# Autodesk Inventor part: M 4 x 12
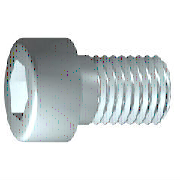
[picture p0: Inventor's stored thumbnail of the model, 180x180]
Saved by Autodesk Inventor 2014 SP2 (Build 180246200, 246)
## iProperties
IsCustomPart: 0
Created: 2009-02
Part Number: M 4 x 12
Material: 강, 연강
Description: 6각머리 태핑 나사
Document SubType Name: Modeling
Standard: KS B 1003
Designer: KYOUNG IL JANG
Standards Organization: KS
Language: ko-KR
Size Designation: M 4 x 12
Categories: <MemberInstance><Categories><Category DisplayName="조임쇠" InternalName="e4da775c-781d-43d5-af7c-5136215cf5a6" Mnemonic="FSTN"><Category DisplayName="볼트" InternalN
Density: 7.86 g/cm^3
Mass: 2.23465 g
Surface Area: 3.30853 cm^2
Volume: 0.284306 cm^3
Appearance: 강철
Author: KYOUNG IL JANG
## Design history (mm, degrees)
sketch "스케치1"
  geometry: L1 (-1, 0)-(12, 0); L2 (12, 0)-(12, 2); L3 (12, 2)-(1.75, 2); L4 (1.75, 2)-(1.32, 2); L5 (1.32, 2)-(0, 2); L6 (0, 2)-(0, 3.5); L7 (0, 3.5)-(-4, 3.5); L8 (-4, 3.5)-(-4, 1.732); L9 (-4, 1.732)-(-2, 1.732); L10 (-2, 1.732)-(-1, 0); L11 (-7.2, 0)-(15.2, 0) reference; L12 (0, -0.7)-(0, 4.2) reference; L13 (1.75, 2)-(0, 2)
  constraints: 22 end point, 6 parallel, 2 collinear, 2 perpendicular, 1 horizontal, 1 point on line
  dimensions: "d1" = 10.25 distance from line of L3.end L2 (= GEL); "d2" = 0.42952 distance of L4.end L3.end (computed from GAL); "d3" = 4 distance between parallel lines of L8 L6 (= KOH); "d4" = 2 distance of L8.end L9.end (= INTI); "d5" = 60 deg angle of L10 L1; "d6" = 4 diameter of L3 L1 (= GD); "d7" = 4 diameter of L5 L1 (= BDM); "d8" = 3.4641 diameter of L9 L1 (= 1.1547 x SW); "d9" = 7 diameter of L7 L1 (= KOD); "d26" = 12 distance between parallel lines of L12 L2 (= NLG)
revolve "본체" sketch "스케치1" stored, may be unused: angle "d10" = 90 deg
sketch "스케치2"
  geometry: L1 (0, -4.9)-(0, 4.9) reference; L2 (-4.9, 0)-(4.9, 0) reference; L3 (1.732, 0)-(0.866, -1.5); L4 (0.866, -1.5)-(-0.866, -1.5); L5 (-0.866, -1.5)-(-1.732, 0); L6 (-1.732, 0)-(-0.866, 1.5); L7 (-0.866, 1.5)-(0.866, 1.5); L8 (0.866, 1.5)-(1.732, 0); 2 further points
  constraints: 12 end point, 1 coincident, 1 horizontal alignment, 1 point on line, 12 other
extrude "슬롯" join sketch "스케치2" stored distance "d11" = 10; taper "d12" = 0 deg
workplane "Work Plane1"
fillet "Fillet2" dims "d30" = 0.1 (= R)
body "Solid1"
fillet "모깎기1" dims "d17" = 0.4 (= RR)
feature "스레드" dims "d13" = 10.25 (= GEL), "d14" = 0
chamfer "모따기1" distance "d15" = 0.42941 (= -0.5 x SPD + 0.5 x GD); stored, may be unused: second distance "d16" = 0.42941 (= GUL), angle "d27" = 45 deg
other parameters: "GD" = 4 (= NND) [user parameter; used in 2 equation terms], "NLG" = 12 [user parameter; used in 1 equation term], "GEL" = 10.25 [user parameter; used in 2 equation terms], "KOD" = 7 [user parameter; used in 1 equation term], "KOH" = 4 [user parameter; used in 1 equation term], "INTI" = 2 [user parameter; used in 1 equation term], "GAL" = 0.42941 (= 0.61345 x PTC) [user parameter; used in 1 equation term], "GUL" = 0.42941 (= 0.61345 x PTC) [user parameter; used in 1 equation term], "BDM" = 4 (= NND) [user parameter; used in 1 equation term], "SW" = 3 [user parameter; used in 2 equation terms], "RR" = 0.4 [user parameter; used in 1 equation term], "SPD" = 3.14117 (= NND - 1.2269 x PTC) [user parameter; used in 1 equation term], "d19" = 0, "d28" = 0, "d29" = 0, "R" = 0.1 [user parameter; used in 1 equation term], "PHH" = 0.2 [user parameter], "GD1" = 3.14117 (= THREADDIA - 1.2269 x PTC) [user parameter], "THREADDIA" = 4 [user parameter; used in 1 equation term], "FAWI" = 45 deg [user parameter], "TPU" = 14.28571 (computed from PTC) [user parameter], "PTC" = 0.7 [user parameter; used in 5 equation terms], "NND" = 4 [user parameter; used in 3 equation terms], "TOA" = 30 deg [user parameter], "E0" = 3.465 (= 1.155 x SW) [user parameter]
